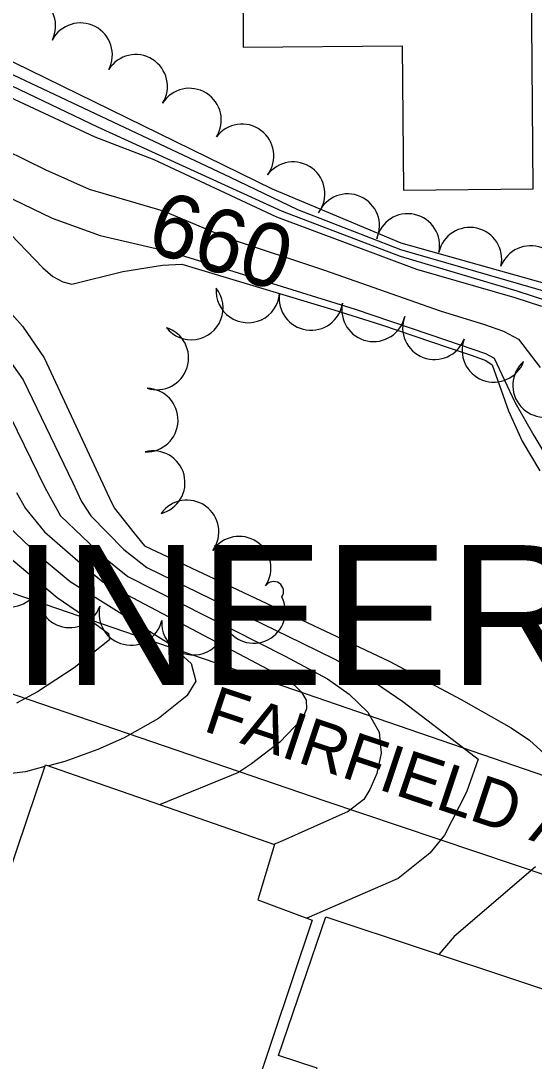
# Model space of a CAD drawing. Extents: x 79600 to 91800, y 75600 to 84400.
# Drawn here: x 86178.2 to 86339.6, y 83164.7 to 83492 of the extents above; entities that cross this region are included whole.
import ezdxf

# ---------------------------------------------------------------- set-up
doc = ezdxf.new("R2010")
doc.units = 0
for name, color, linetype in [('084-085$0$TI_CCLOGO', 7, 'Continuous'), ('084-090$0$BLDG', 7, 'Continuous'), ('084-090$0$INDEX', 7, 'Continuous'), ('084-090$0$INDXLBL', 7, 'Continuous'), ('084-090$0$INTER', 7, 'Continuous'), ('084-090$0$ROAD', 7, 'Continuous'), ('084-090$0$ROAD-NAME', 7, 'Continuous'), ('084-090$0$TREES', 7, 'Continuous')]:
    doc.layers.add(name, color=color, linetype=linetype)

msp = doc.modelspace()

# ---------------------------------------------------------------- linework, layer by layer
at = {"layer": '084-090$0$BLDG'}
for points in [[(86238.81, 83504.8), (86247.98, 83504.88), (86248.16, 83483.62), (86298.15, 83484.03), (86298.53, 83438.72), (86339.3, 83439.06), (86338.32, 83556.95), (86238.39, 83556.12)], [(86224.34, 83075.53), (86129.86, 83106.71), (86139.29, 83136.6), (86144.4, 83134.8), (86185.95, 83257.94), (86257.98, 83232.87), (86252.75, 83215.38), (86269.8, 83209.06), (86238.46, 83115.5), (86230.85, 83119.44), (86223.17, 83099.76), (86231.07, 83097.06)], [(86271.35, 82895.67), (86189.25, 82923.42), (86271.34, 83162.45), (86259.26, 83166.5), (86274.11, 83210.03), (86365.03, 83179.9)]]:
    msp.add_lwpolyline(points, close=True, dxfattribs=at)
at = {"layer": '084-090$0$INDEX'}
for points in [[(86013.8, 83496.71), (86022.71, 83487.89), (86030.34, 83481.8), (86033.37, 83479.59), (86061.94, 83481.23), (86088.48, 83479.31), (86123.96, 83471.02), (86130.98, 83469.37), (86160.41, 83457.63), (86186.07, 83445.04), (86199.66, 83438.94), (86222.97, 83432.17), (86243.45, 83423.53), (86273.73, 83413.51), (86310.11, 83400.69), (86323.95, 83396.41), (86329.94, 83394.31), (86334.65, 83391.85), (86341.49, 83382.89)], [(86120.32, 83493.27), (86201.43, 83455.42), (86220.08, 83448.32), (86258.58, 83430.31), (86302.65, 83413.83), (86333.49, 83404.91), (86341.89, 83402.22)], [(86159.76, 83440.54), (86185.08, 83414.22), (86188.31, 83411.51), (86191.42, 83409.79), (86194.27, 83409.08), (86210.25, 83413.09), (86222.72, 83415.13), (86228.79, 83415.43), (86276.59, 83401), (86291.64, 83396.36), (86312.53, 83389.22), (86320.11, 83386.63), (86324.45, 83385.05), (86326.38, 83383.71), (86331.54, 83369.31), (86335.8, 83359.68), (86341.43, 83350.35)], [(86174.16, 83333.04), (86183.64, 83323.91), (86193.68, 83315.61), (86224.8, 83296.04), (86231.81, 83289.79), (86233.21, 83284.26), (86230.41, 83279.59), (86221.45, 83272.5), (86210.65, 83266.41), (86202.43, 83262.74), (86192.04, 83258.98), (86186.86, 83257.63)], [(86185.74, 83257.33), (86179.65, 83255.74), (86135.32, 83250.43), (86131.34, 83249.64), (86125.16, 83241.02), (86118.72, 83230.33), (86112.78, 83216.12), (86097.23, 83191.67), (86085.56, 83168.46), (86070.22, 83150.05), (86058.41, 83123.76), (86052.69, 83110.68), (86046.58, 83099.69), (86033.94, 83082.63), (86032.64, 83080.28)]]:
    msp.add_lwpolyline(points, dxfattribs=at)
at = {"layer": '084-090$0$INTER'}
for points in [[(86119.9, 83506.38), (86257.24, 83439.09), (86297.68, 83422.12), (86346.23, 83408.45)], [(86116.78, 83502.84), (86243.98, 83442.72), (86265.24, 83432.61), (86297.56, 83420.02), (86344.78, 83406.37)], [(85990.87, 83497.57), (85998.5, 83486.74), (86006.97, 83476.74), (86015.3, 83468.85), (86024.83, 83461.73), (86028.13, 83459.86), (86046.22, 83464.96), (86059.18, 83466.41), (86065.45, 83466.68), (86086.14, 83463.25), (86107.67, 83457.03), (86133.24, 83452.45), (86157.15, 83444.78), (86188.09, 83429.91), (86203.13, 83424.42), (86225.28, 83419.24), (86283.32, 83401.25), (86312.05, 83391.51), (86324.35, 83387.33), (86327.09, 83385.83), (86333.53, 83372.02), (86339.46, 83361.48), (86344.7, 83352.81)], [(86121.14, 83497.45), (86202.32, 83458.57), (86260.42, 83432.12), (86297.44, 83417.92), (86334.2, 83407.03), (86348.65, 83402.28)], [(86172.73, 83402.57), (86178.72, 83395.84), (86185.52, 83385.98), (86206.06, 83341.8), (86207.57, 83338.73), (86213.88, 83330.74), (86217.09, 83326.79), (86294.07, 83290.49), (86316.65, 83278.4), (86332.42, 83269.54), (86338.12, 83265.63), (86345.13, 83259.21)], [(86172.88, 83387.64), (86178.96, 83379.04), (86194.56, 83346.59), (86197.25, 83340.7), (86200.27, 83336.2), (86210.6, 83325.61), (86217.86, 83319.99), (86266.5, 83296.3), (86276.98, 83291.14), (86287.69, 83285.04), (86298.36, 83277.85), (86315.21, 83264.95), (86321.02, 83260.43), (86322, 83259.65), (86318.34, 83249.3), (86311.47, 83235.73), (86306.79, 83230.08), (86296.86, 83222.14), (86268.18, 83209.66)], [(86172.73, 83371.8), (86185.72, 83345.09), (86190.67, 83336.18), (86204.32, 83323.25), (86211.87, 83317.19), (86261.28, 83292.06), (86274.68, 83284.91), (86281.49, 83280.12), (86287.29, 83274.51), (86290.9, 83268.22), (86291.54, 83261.52), (86290.12, 83255.2), (86287.97, 83250.15), (86286.1, 83246.96), (86281.17, 83243.25), (86259.54, 83233.53), (86257.9, 83232.9)], [(86176.88, 83343.59), (86179.65, 83338.5), (86185.67, 83331.15), (86197.73, 83320.72), (86204.05, 83315.34), (86256.06, 83287.84), (86261.43, 83284.97), (86264.16, 83283.05), (86266.48, 83280.8), (86267.93, 83278.28), (86268.08, 83275.52), (86266.78, 83272.44), (86259.66, 83265.05), (86250.78, 83258.23), (86246.6, 83255.47), (86222, 83245.4)], [(86171.07, 83326.09), (86189.63, 83310.49), (86199.93, 83303.52), (86205.77, 83299.25), (86206.13, 83297.27), (86195.02, 83288.46), (86183.43, 83280.85), (86176.87, 83277.31)], [(86340.04, 83225.83), (86314.5, 83203.86), (86309.65, 83198.25)]]:
    msp.add_lwpolyline(points, dxfattribs=at)
at = {"layer": '084-090$0$ROAD'}
for points in [[(86431.68, 83223.82), (86267.71, 83280.21), (86054.7, 83353.29), (85915.58, 83401.79), (85906.58, 83407.1), (85905.43, 83408.43)], [(86319.76, 82887.35), (86421.65, 83169.03), (86422.2, 83175.68), (86420.87, 83184.77), (86416.94, 83192.45), (86404.18, 83202.67), (86273.91, 83246.46), (85940.07, 83360.81), (85932.64, 83362.59), (85926.63, 83362.06), (85920.18, 83357.98), (85913.76, 83351.59), (85910.43, 83344.77), (85908.04, 83336.87), (85908.01, 83324.98), (85918.99, 83150.63)]]:
    msp.add_lwpolyline(points, dxfattribs=at)
at = {"layer": '084-090$0$TREES'}
for centre, radius, start, end in [((86179.15, 83490.32), 10, 333.8344, 153.8344), ((86196.98, 83481.28), 10, 332.413, 152.413), ((86214.31, 83471.34), 9.99, 327.912, 147.912), ((86231.24, 83460.72), 10, 327.912, 147.912), ((86247.75, 83449.46), 10, 323.4545, 143.4545), ((86263.82, 83437.55), 10, 323.4552, 143.4552), ((86280.98, 83427.5), 10, 335.8641, 155.8641), ((86299.87, 83421.26), 10, 347.5415, 167.5415), ((86319.4, 83416.95), 10, 347.5624, 167.5624), ((86338.49, 83411.18), 10, 338.8505, 158.8505), ((86231.81, 83401.63), 10, 218.382, 38.382), ((86249.61, 83406.97), 10, 175.0051, 355.0051), ((86269.46, 83404.6), 10, 171.4163, 351.4163), ((86289.13, 83401.04), 10, 168.0313, 348.0313), ((86308.26, 83395.41), 10, 159.1902, 339.1902), ((86220.96, 83385.88), 10, 252.4752, 72.4752), ((86326.96, 83388.3), 10, 159.1858, 339.1858), ((86342.91, 83377.24), 10, 131.3581, 311.3581), ((86217.64, 83366.35), 10, 268.2561, 88.2561), ((86219.83, 83346.67), 10, 284.404, 104.404), ((86230.45, 83331.17), 10, 324.439, 144.439), ((86246.87, 83319.77), 9.99, 326.0074, 146.0074), ((86174.67, 83317.55), 10, 161.0609, 341.0609), ((86193.59, 83311.06), 10, 161.0609, 341.0609), ((86257.72, 83312.45), 3.11, 326.0074, 146.0074), ((86212.79, 83305.55), 10, 166.9411, 346.9411), ((86251.38, 83306.18), 10, 206.8997, 26.8997), ((86232.5, 83302.48), 10, 175.317, 355.317)]:
    msp.add_arc(centre, radius, start, end, dxfattribs=at)

# ---------------------------------------------------------------- texts
at = {"layer": '084-085$0$TI_CCLOGO'}
msp.add_text('CUYAHOGA COUNTY ENGINEER', height=44, dxfattribs=at).set_placement((85430, 83283))
at = {"layer": '084-090$0$INDXLBL'}
msp.add_text('660', height=20, rotation=342.8079, dxfattribs=at).set_placement((86216.94, 83419.84))
at = {"layer": '084-090$0$ROAD-NAME'}
msp.add_text('FAIRFIELD AVE.', height=15, rotation=341.5003, dxfattribs=at).set_placement((86235.16, 83268.72))

doc.saveas('drawing.dxf')
